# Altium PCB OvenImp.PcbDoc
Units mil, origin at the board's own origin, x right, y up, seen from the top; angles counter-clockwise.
Board outline 3800 x 1750 mil, 2 copper layers (Top Layer, Bottom Layer); 45 components, 37 nets, 177 pads, 107 vias.
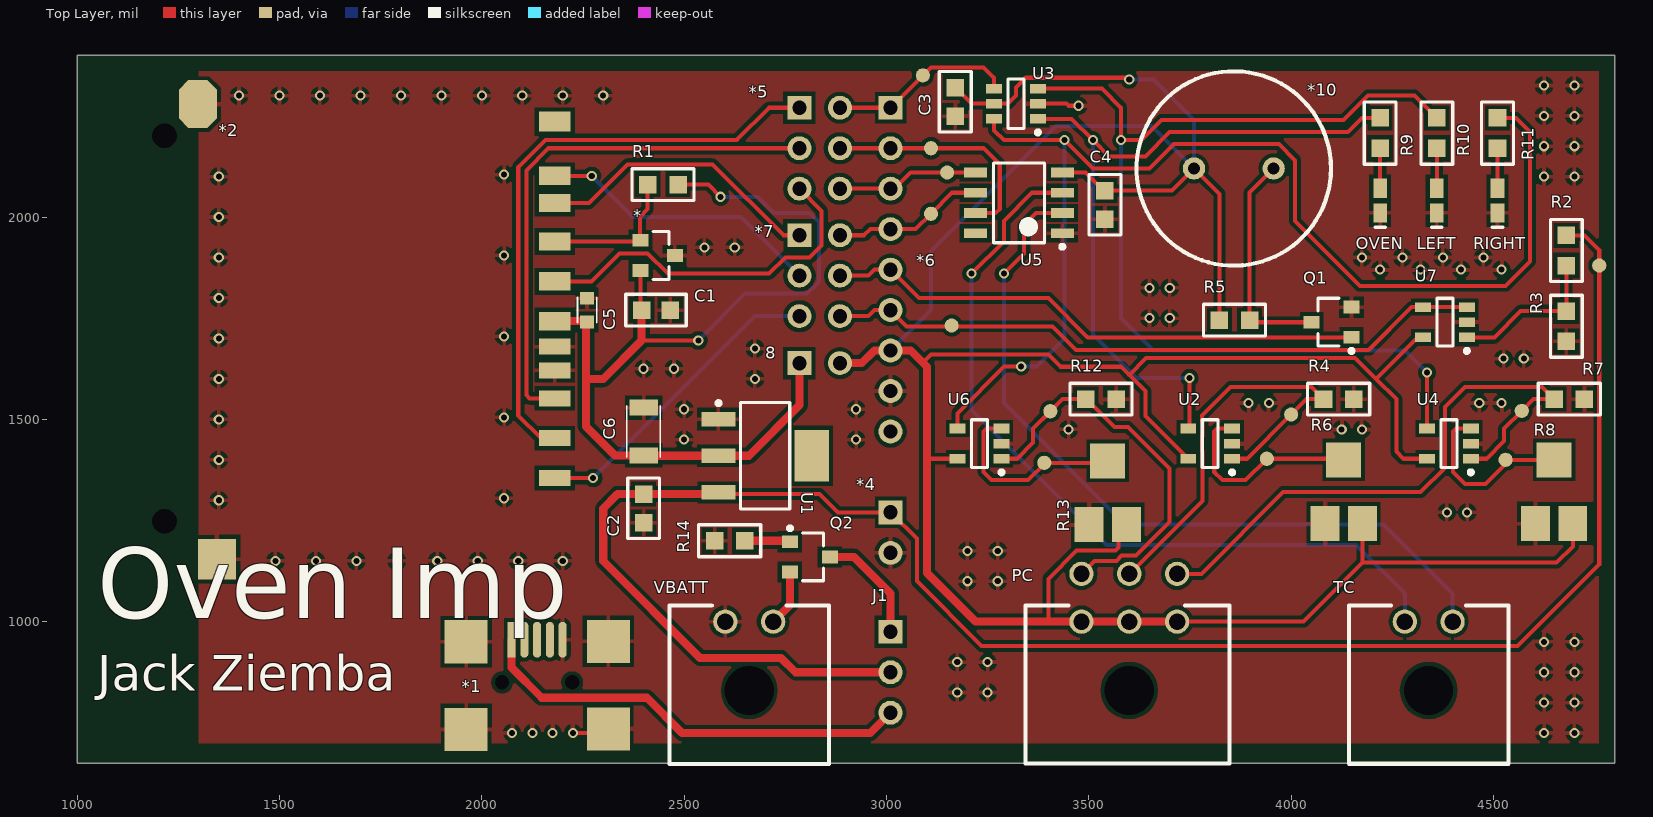
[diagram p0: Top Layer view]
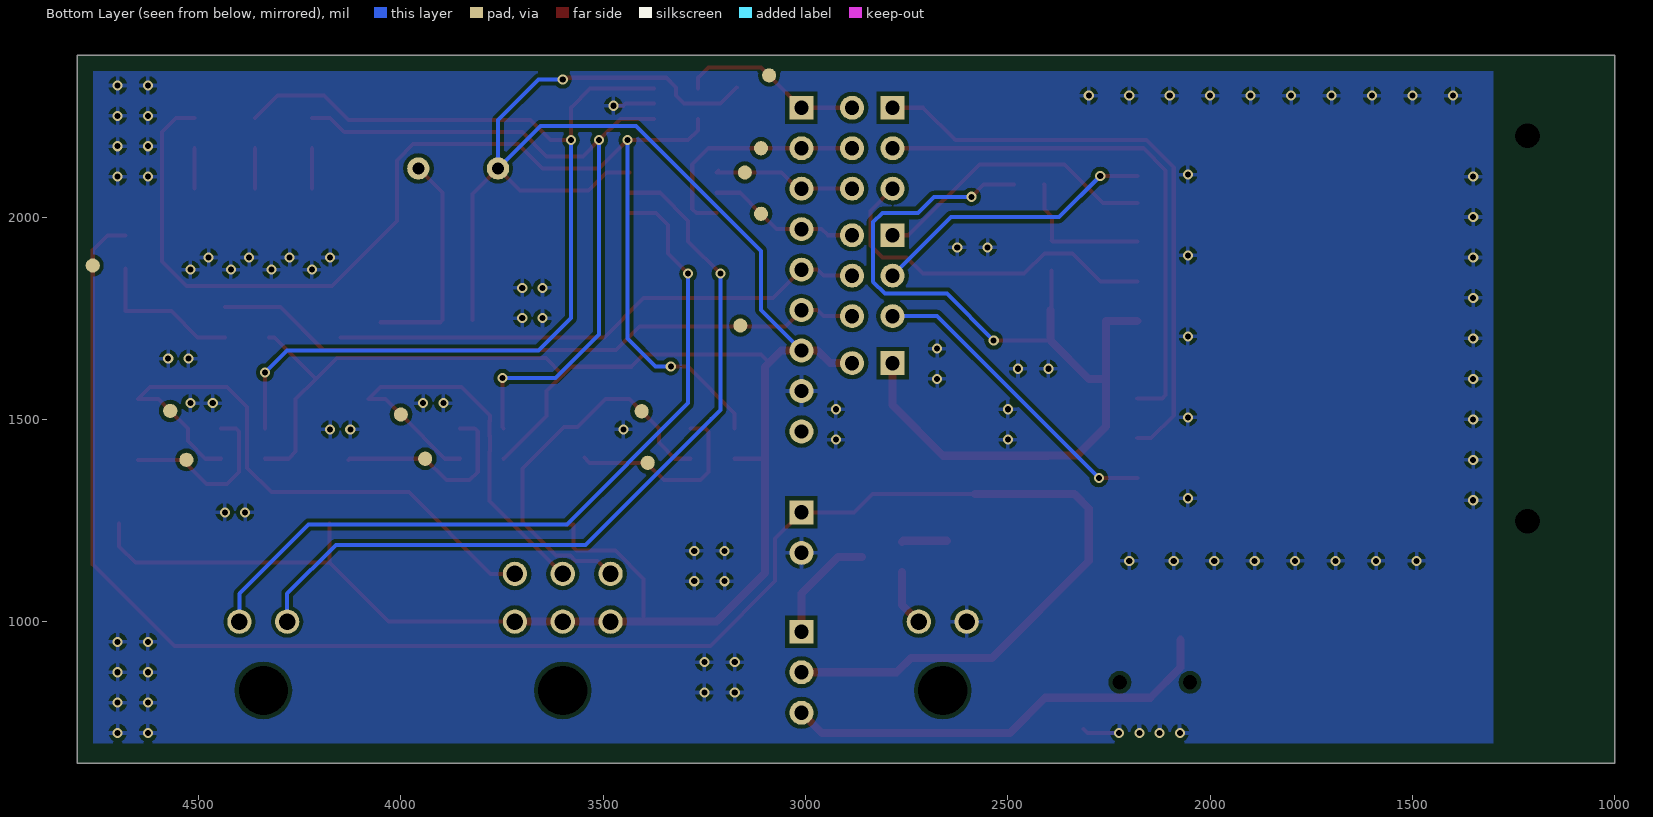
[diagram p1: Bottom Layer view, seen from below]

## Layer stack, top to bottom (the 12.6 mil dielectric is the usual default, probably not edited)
Top Solder: solder mask 0.4, Solder Resist, Dk 3.5
Top Layer: signal copper 1.4
Dielectric 1: dielectric 12.6, FR-4, Dk 4.8
Bottom Layer: signal copper 1.4
Bottom Solder: solder mask 0.4, Solder Resist, Dk 3.5

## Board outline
1000,650 1000,2400 4800,2400 4800,650

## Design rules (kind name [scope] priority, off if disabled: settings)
Clearance [All] p1: gap=8
HoleSize [All] p1: absolutevalues=TRUE maxlimit=200 minlimit=1 maxpercent=80.000 minpercent=20.000
MinimumAnnularRing [All] p1: minimumring=5
PolygonConnect PolygonConnect_2 [All vs IsNamedPolygon('BTM_GND')] p1: connectstyle=Relief reliefconductorwidth=15 reliefentries=4 polygonreliefangle="90 Angle" airgapwidth=10
PolygonConnect PolygonConnect_1 [All vs IsNamedPolygon('TOP_GND')] p2: connectstyle=Relief reliefconductorwidth=15 reliefentries=4 polygonreliefangle="90 Angle" airgapwidth=10
PolygonConnect [All] p3: connectstyle=Relief reliefconductorwidth=10 reliefentries=4 polygonreliefangle="90 Angle" airgapwidth=10
RoutingVias [All] p1: holewidth=25 width=25 viastyle="Through Hole" minholewidth=10 minwidth=15 maxholewidth=30 maxwidth=50
SilkToSilkClearance [All] p1: silktosilkclearance=5
SolderMaskExpansion [All] p1: expansion=6
Width [All] p1: maxlimit=200 minlimit=10 preferedwidth=10
28 further rules are at their usual default settings.

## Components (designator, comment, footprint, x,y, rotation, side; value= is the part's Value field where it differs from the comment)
8 "2 pin header" HDR254P1X2-N 2785,1639 r0 top
* "Crypto ID" SOT23-ATMEL 2435,1905 r180 top
*1 "Mini_USB" 4ucon20035 2137.11,844.59 r0 top
*2 "Imp_Slot" IMP_SLOT_COMBO 1570,1720 r90 top
*4 "2 pin header" HDR254P1X2-N 3010,1270 r270 top
*5 "2 pin header_1" HDR254P2X3-N 2785,2270 r270 top
*6 "April_breakout" HDR254P1X9-N 3010,2270 r270 top
*7 "2 pin header_1" HDR254P2X3-N 2785,1955 r270 top
*10 "AUDIO PIEZO TRANSDUCER 30V TH" "Piezo Buzzer" 3760,2120 r0 top
C1 "0.1uF" 0603_CAPACITOR 2430.43,1770 r180 top
C2 "0.1uF" 0603_CAPACITOR 2400,1280 r90 top
C3 "0.1uF" 0603_CAPACITOR 3170,2284.57 r90 top
C4 "0.1uF" 0603_CAPACITOR 3540,2030 r90 top
C5 "311-1446-1-ND" CAP0603 2260,1770 r270 top
C6 "CC1206ZKY5V7BB106" CAP1206 2400,1470 r270 top
J1 "3 Pin header" HDR254P1X3-N 3010,975 r270 top
LEFT "LED" DIOM1608X03N 4360,2040.51 r90 top
OVEN "LED" DIOM1608X03N 4220,2040.51 r90 top
PC "6 pin mate n lok" 3-794620-6 3481.89,1000.08 r0 top
Q1 "MOSFET N-CH 60V 1.3A SOT23F" SOT95P240X100-3N 4100,1730 r0 top
Q2 "PFET_GOOD" SOT95P240X100-3N 2810.79,1170 r180 top
R1 "100K" 0603_Resistor 2447.6,2080 r0 top
R2 "2K" 0603_Resistor 4680,1917.4 r90 top
R3 "1K" 0603_Resistor 4680,1730 r90 top
R4 "10K" 0603_Resistor 4117.4,1550 r180 top
R5 "1K" 0603_Resistor 3860,1745 r180 top
R6 "TRIMMER 10K OHM 0.25W SMD" "SMD Trimpot" 4130,1242.52 r0 top
R7 "10K" 0603_Resistor 4687.4,1550 r180 top
R8 "TRIMMER 10K OHM 0.25W SMD" "SMD Trimpot" 4650,1242.52 r0 top
R9 "RC0603FR-07220RL" 0603_Resistor 4220,2207.4 r90 top
R10 "RC0603FR-07220RL" 0603_Resistor 4360,2207.4 r90 top
R11 "RC0603FR-07220RL" 0603_Resistor 4510,2207.4 r90 top
R12 "10K" 0603_Resistor 3530,1550 r180 top
R13 "TRIMMER 10K OHM 0.25W SMD" "SMD Trimpot" 3546.74,1240 r0 top
R14 "100K" 0603_Resistor 2612.6,1200 r0 top
RIGHT "LED" DIOM1608X03N 4510,2040.51 r90 top
TC "2pin Micro mate n lok" 3-794620-2 4280.94,1000.08 r0 top
U1 "IC REG LDO 3V3 1A" SOT230P700X180-4N 2700,1410 r0 top
U2 "IC COMPARATOR VOLT SGL SOT23-5" SOT95P280X145-5N 3800,1440 r180 top
U3 "IC OR GATE 3 INPUT SOT23-6" SOT95P280X145-6N 3320,2280 r180 top
U4 "IC COMPARATOR VOLT SGL SOT23-5" SOT95P280X145-5N 4390,1440 r180 top
U5 "IC CONV THERMOCOUPLE-DGTL SOIC" SOIC127P600X175-8N 3327.28,2035 r180 top
U6 "IC COMPARATOR VOLT SGL SOT23-5" SOT95P280X145-5N 3230,1440 r180 top
U7 "IC OPAMP GP 1.3MHZ RRO SOT23-5" SOT95P280X145-5N 4380,1740 r180 top
VBATT "2pin Micro mate n lok" 3-794620-2 2601.89,1000 r0 top

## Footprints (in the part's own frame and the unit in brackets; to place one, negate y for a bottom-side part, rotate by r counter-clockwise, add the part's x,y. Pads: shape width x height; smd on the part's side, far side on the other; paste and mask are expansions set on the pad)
3-794620-2 [mm] "2 Pin TE Micro Mate-N-Lok"
  round 1.524 hole 1.03: 1(3,0) 2(0,0)
  round 0 hole 3.08 paste+0: HOLE(1.5,-4.32)
  silkscreen extent -3.5,-8.92 6.5,1.02
3-794620-6 [mm] "6 Pin TE Micro Mate-N-Lok"
  round 1.524 hole 1.03: 1(6,0) 2(3,0) 3(0,0) 4(0,3) 5(3,3) 6(6,3)
  round 0 hole 3.08 paste+0: HOLE(3,-4.32)
  silkscreen extent -3.5,-8.9 9.3,1
4ucon20035 [mm] "Mini-B USB, Top Mount, Right Angle, SMT"
  rect 0.5x2.25 smd: 1(-1.612,2.813)
  oval 0.5x2.25 smd: 2(-0.812,2.813) 3(-0.012,2.813) 4(0.788,2.813) 5(1.588,2.813)
  round 0 hole 0.9 unplated paste+0 mask+1: H1(-2.213,0.138)
  round 0 hole 0.9 unplated mask+1: H2(2.188,0.138)
  rect 2.7x2.7 smd: M1(-4.463,2.688) M2(4.463,2.712) M3(-4.463,-2.812) M4(4.463,-2.788)
  body extent -4.95,-5.77 4.95,3.23, height 4.08
0603_CAPACITOR [mm]
  rect 1.1x1.1 smd: 1(-0.9,0) 2(0.9,0)
  silkscreen extent -1.9,-1 1.9,1, body extent -0.8,-0.37 0.8,0.43, height 0.6
0603_Resistor [mm]
  rect 1.1x1.1 smd: 1(-0.95,0) 2(0.95,0)
  silkscreen extent -1.95,-1 1.95,1, body extent -0.8,-0.37 0.8,0.43, height 0.46
CAP0603 [mm] "Chip Capacitor, Body 1.6x0.8mm"
  rect 0.8x0.9 smd: 1(-0.75,0) 2(0.75,0)
  silkscreen extent -0.8,-0.6 0.8,0.6, body extent -0.87,-0.45 0.83,0.45, height 0.9
CAP1206 [mm] "Chip Capacitor, Body 3.2x1.6mm"
  rect 1x1.8 smd: 1(-1.5,0) 2(1.5,0)
  silkscreen extent -1.6,-1.05 1.6,1.05, body extent -1.65,-0.85 1.65,0.85, height 0.95
DIOM1608X03N [mm] "Molded Diode, 2-Leads, Body 1.6x0.8mm, IPC Medium Density"
  rect 1.2x0.85 smd: 1(-0.775,0) 2(0.775,0)
  silkscreen extent -1.68,-0.33 -1.68,0.33, body extent -0.85,-0.45 0.85,0.45, height 0.35
HDR254P1X2-N [mm] "HDR, 2.54mm Pitch, 2-Pin"
  rect 1.5x1.5 hole 0.9: 1(0,0)
  round 1.5 hole 0.9: 2(2.54,0)
  body extent -1.27,-1.27 3.81,1.27, height 8.54
HDR254P1X3-N [mm] "HDR, 2.54mm Pitch, 3-Pin"
  rect 1.5x1.5 hole 0.9: 1(0,0)
  round 1.5 hole 0.9: 2(2.54,0) 3(5.08,0)
  body extent -1.27,-1.27 6.35,1.27, height 8.54
HDR254P1X9-N [mm] "HDR, 2.54mm Pitch, 9-Pin"
  rect 1.5x1.5 hole 0.9: 1(0,0)
  round 1.5 hole 0.9: 2(2.54,0) 3(5.08,0) 4(7.62,0) 5(10.16,0) 6(12.7,0) 7(15.24,0) 8(17.78,0) 9(20.32,0)
  body extent -1.27,-1.27 21.59,1.27, height 8.54
HDR254P2X3-N [mm] "HDR, 2.54mm Pitch, 2x3-Pin"
  rect 1.5x1.5 hole 0.9: 1(0,0)
  round 1.5 hole 0.9: 2(0,2.54) 3(2.54,0) 4(2.54,2.54) 5(5.08,0) 6(5.08,2.54)
  body extent -1.27,-1.27 6.35,3.81, height 8.54
IMP_SLOT_COMBO [mm] "Combo Footprint for Kyocera, Proconn and 4UConn"
  rect 1x2 smd: 1(-6.77,-15.5) 2(-4.27,-15.5) 3(-2.52,-15.5) 9(-9.27,-15.5) 10(-1.02,-15.5)
  rect 1.15x2 smd: 4(0.575,-15.5) 5(3.075,-15.5) 6(5.575,-15.5) 7(7.995,-15.5) 8(9.695,-15.5)
  rect 1.25x2 smd: 11(13.095,-15.5)
  oct 3x2.4 smd: 12(14.2,6.9)
  rect 2.55x2.4 smd: 13(-14.375,5.7)
  round 0 hole 1.55 unplated: 14(-11.98,9) 15(12.22,9)
  body extent -14.55,-15.75 13.95,14.5, height 2.65
"Piezo Buzzer" [mm]
  round 1.4 / inner round 1.3 / far side round 1.4 hole 0.75: 1(0,0) 2(5,0)
  silkscreen extent -3.6,-6.1 8.6,6.1, body extent -3.54,-6.08 8.62,6.08, height 7.5
"SMD Trimpot" [mm]
  rect 1.8x2.2 smd: 1(-1.175,0) 3(1.175,0)
  rect 2.2x2.2 smd: 2(0,4)
  body extent -1.9,-0.29 1.9,4.21, height 1.4
SOIC127P600X175-8N [mm] "SOIC, 8-Leads, Body 4.90x3.90mm, Pitch 1.27mm, IPC Medium Density"
  rect 1.45x0.6 smd: 1(-2.725,1.905) 2(-2.725,0.635) 3(-2.725,-0.635) 4(-2.725,-1.905) 5(2.725,-1.905) 6(2.725,-0.635) 7(2.725,0.635) 8(2.725,1.905)
  silkscreen extent -2.85,-2.5 1.6,2.88, body extent -3,-2.5 3,2.5, height 1.75
SOT23-ATMEL [mm] "SOT23 ATSHA204 pinout"
  rect 1x0.8 smd: 1(1.075,-0.95) 2(1.075,0.95) 3(-1.075,0)
  silkscreen extent -0.7,-1.5 0.3,1.5, body extent -1.17,-1.46 1.17,1.46, height 1
SOT95P240X100-3N [mm] "SOT23, 3-Leads, Body 2.90x2.40mm, Pitch 0.95mm, IPC Medium Density"
  rect 1x0.8 smd: 1(1.25,-0.696) 2(1.25,1.204) 3(-1.25,0.254)
  silkscreen extent -0.85,-1.67 1.38,1.75, body extent -1.25,-1.25 1.25,1.75, height 1
SOT95P280X145-5N [mm] "SOT23, 5-Leads, Body 2.90x2.80mm, Pitch 0.95mm, IPC Medium Density"
  rect 1x0.6 smd: 1(-1.375,0.95) 2(-1.375,0) 3(-1.375,-0.95) 4(1.375,-0.95) 5(1.375,0.95)
  silkscreen extent -1.5,-1.5 0.5,1.92, body extent -1.5,-1.5 1.5,1.5, height 1.45
SOT95P280X145-6N [mm] "SOT23, 6-Leads, Body 2.90x2.80mm, Pitch 0.95mm, IPC Medium Density"
  rect 1x0.6 smd: 1(-1.375,0.95) 2(-1.375,0) 3(-1.375,-0.95) 4(1.375,-0.95) 5(1.375,0) 6(1.375,0.95)
  silkscreen extent -1.5,-1.55 0.5,1.92, body extent -1.5,-1.53 1.5,1.53, height 1.45
SOT230P700X180-4N [mm] "SOT223, 4-Leads, Body 6.50x7.00mm (avg), Pitch 2.30mm, IPC Medium Density"
  rect 2.15x0.9 smd: 1(-2.925,2.3) 2(-2.925,0) 3(-2.925,-2.3)
  rect 2.15x3.25 smd: 4(2.925,0)
  silkscreen extent -3.05,-3.35 1.55,3.42, body extent -3.5,-3.35 3.5,3.35, height 1.8

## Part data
C1 C2 C3 C4: library part "CAP CER 0.1UF 50V Y5V 0603", "0.1UF CAP 0603"
C5: library part CC0603KRX7R7BB105, "CAP CER 1UF 16V 10% X7R 0603"
C6: "CAP CER 10UF 16V Y5V 1206"
LEFT OVEN RIGHT: library part LTST-C193KRKT-5A, "LED RED RECT CLEAR 0603"
R1 R14: library part "RES SMD 100K OHM 5% 1/10W 0603", "100K OHM Resistor 5%, 1/10W 0603"
R2: library part "RES SMD 2K OHM 5% 1/10W 0603", "2K OHM Resistor 5%, 1/10W 0603"
R3 R5: library part "RES SMD 1K OHM 5% 1/10W 0603", "1K OHM Resistor 5%, 1/10W 0603"
R4 R7 R12: library part "RES SMD 10K OHM 5% 1/10W 0603", "10K OHM Resistor 5%, 1/10W 0603"
R9 R10 R11: "RES 220 OHM 1/10W 1% 0603 SMD"
U1: "3.3V LDO SOT223"
U2 U4 U6: "Comparator SOT23"
U3: "OR Gate 3 Input"
U5: "Thermocouple to Digital Converter"
U7: "OPAMP SOT23"

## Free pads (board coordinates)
  round 35 all layers, no hole: 2(3090,2350) 2(3110,2008) 2(3110,2170) 2(3150,2110) 2(3161,1732) 2(3390,1392.6) 2(3405,1520) 2(3940,1402.6) 2(4000,1512) 2(4530,1400) 2(4570,1521) 2(4761.46,1880)

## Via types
v1: diameter 25, hole 15, Top Layer to Bottom Layer, tented both sides, 94 vias
v2: diameter 25, hole 15, Top Layer to Bottom Layer, 13 vias

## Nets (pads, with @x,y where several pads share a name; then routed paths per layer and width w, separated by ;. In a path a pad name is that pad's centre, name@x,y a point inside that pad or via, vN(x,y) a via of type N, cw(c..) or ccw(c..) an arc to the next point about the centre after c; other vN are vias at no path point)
3V3: 8.2 *6.7 *10.1 C3.2 C4.2 PC.1 PC.2 PC.3 R5.2 R6.3 R8.3 R13.3 U2.5 U3.5 U4.5 U5.4 U6.5 U7.5 | length 7682.8
  Top Layer w10: 3090,1640 3110,1660 3400,1660 3430,1630 3580,1630 3600,1610 ; 3100,1390 3102.6,1392.6 ; 3100,1410 3107.4,1402.6 U6.5 ; C3.2 3210,2280 U3.5 3300,2280 3320,2300 3320,2320 3344.21,2344.21 3595.79,2344.21 v2(3600,2340) ; 3400,1000.08 3400,1106 3470,1176 3565.89,1176 3573.08,1183.19 3573.08,1240 R13.3 ; U5.4 3491.72,2110 3536.28,2065.43 C4.2 3705.43,2065.43 *10.1 3822.6,2057.4 R5.2 ; PC.1 4030.08,1000.08 4176.26,1146.26 ; U2.5 3640,1508.47 3640,1570 3600,1610 ; R6.3 4176.26,1146.26 ; U7.5 4312.6,1702.6 4210,1600 ; U4.5 4277.4,1402.6 4260,1420 4260,1550 4210,1600 ; R8.3 4696.26,1186.26 4656.26,1146.26 4176.26,1146.26 ; 3600,1610 3641.85,1651.85 4158.15,1651.85 4210,1600
  Top Layer w20: 8.2 2939,1639 2970,1670 *6.7 3060,1670 3090,1640 3100,1630 3100,1410 3100,1390 3100,1120 3219.92,1000.08 3400,1000.08 PC.3 PC.2 PC.1
  Bottom Layer w10: *6.7 3110,1770 3110,1916.57 3418.43,2225 3655,2225 *10.1 3760,2240 3660,2340 v2(3600,2340)
3V3_I: 8.1 *2.4 *.2 C1.2 C5.2 C6.2 R1.2 U1.2 | length 2432.7
  Top Layer w10: *.2 2392.68,1772.32 C1.2 ; 2395,1695 v2(2535,1695) ; R1.2 2560,2080 v2(2590,2050)
  Top Layer w20: *2.4 2257.83,1742.64 2257.83,1600 ; C1.2 2395,1695 2300,1600 2257.83,1600 ; 8.1 2785,1535 2660,1410 U1.2 2400.94,1410 C6.2 2329.06,1410.94 2257.83,1482.17 2257.83,1600
  Bottom Layer w10: v2(2535,1695) 2650.47,1810.47 2803.44,1810.47 2832.97,1840 2832.97,1987.3 2810.27,2010 2722.03,2010 2682.03,2050 v2(2590,2050)
ALARM: *6.5 *7.4 Q1.1 | length 1339.8
  Top Layer w10: *7.4 2955,1855 2970,1870 *6.5 3080,1800 3400,1800 3497.4,1702.6 Q1.1
ALARM_I: *2.8 *7.3 | length 706.9
  Top Layer w10: *2.8 v2(2271.69,2101.69)
  Bottom Layer w10: v2(2271.69,2101.69) 2373.39,2000 2640,2000 *7.3
BATT_VOLTAGE: *6.6 *7.6 pad.2@3161,1732 U7.3 U7.4 | length 1639.7
  Top Layer w10: *7.6 2955,1755 2970,1770 *6.6 3050,1730 3410,1730 3468.15,1671.85 4191.85,1671.85 4297.4,1777.4 U7.4 U7.3
BATT_VOLTAGE_I: *2.9 *7.5 | length 770.4
  Top Layer w10: *2.9 v2(2275.04,1355.04)
  Bottom Layer w10: v2(2275.04,1355.04) 2675,1755 *7.5
C\S\: *6.4 *7.2 pad.2@3110,2008 U5.6 | length 378.5
  Top Layer w10: *7.2 2945,1955 2960,1970 *6.4 3072,1970 3110,2008 3162,2060 U5.6
C\S\_I: *2.7 *7.1 | length 716.7
  Top Layer w10: *2.7 2264.76,2034.76 2360,2130 2570,2130 2745,1955 *7.1
GND: *1.5 *1.M1 *1.M2 *1.M3 *1.M4 *2.3 *2.10 *2.12 *2.13 *4.2 *6.8 *.3 C1.1 C2.1 C3.1 C4.1 C5.1 C6.1 LEFT.1 OVEN.1 Q1.2 R3.1 R4.1 R6.1 R7.1 R8.1 R12.1 R13.1 R14.1 RIGHT.1 U1.1 U2.2 U3.2 U4.2 U5.1 U6.2 U7.2 VBATT.2 | length 194.8
  Top Layer w10: v1(2225,725) 2302.95,725 *1.M4 ; U3.2 3445,2280 3450,2275 v1(3475,2275)
  other v1: 2075,725 2125,725 2175,725 4625,725 4700,725 4625,800 4700,800 3175,825 3250,825 4625,875 4700,875 3175,900 3250,900 4625,950 4700,950 3200,1100 3275,1100 1490,1150 1590,1150 1690,1150 1790,1150 1890,1150 1990,1150 2090,1150 2200,1150 3200,1175 3275,1175 4385,1270 4435,1270 1350,1300 2055,1305 1350,1400 2500,1450 2925,1450 3450,1475 4125,1475 4175,1475 1350,1500 2055,1505 2500,1525 2925,1525 3895,1540 3945,1540 4465,1540 4520,1540 1350,1600 2675,1600 2400,1625 2475,1625 4525,1650 4575,1650 2675,1675 1350,1700 2055,1705 3650,1750 3700,1750 1350,1800 3650,1825 3700,1825 4220,1870 4320,1870 4420,1870 4520,1870 1350,1900 4175,1900 4275,1900 4375,1900 4475,1900 2055,1905 2550,1925 2625,1925 1350,2000 1350,2100 4625,2100 4700,2100 2055,2105 4625,2175 4700,2175 4625,2250 4700,2250 1400,2300 1500,2300 1600,2300 1700,2300 1800,2300 1900,2300 2000,2300 2100,2300 2200,2300 2300,2300 4625,2325 4700,2325
LEFT_LIGHT: R10.2 U3.3 U4.4 | length 2533.8
  Top Layer w10: U3.3 3532.6,2317.4 3580,2270 v2(3580,2190) 3630,2190 3680,2240 4130,2240 4190,2300 4304.8,2300 R10.2 ; U4.4 v2@4335.87,1605.87
  Bottom Layer w10: v2(3580,2190) 3580,1750 3660,1670 4281.73,1670 v2(4335.87,1615.87)
LEFT_LIGHT_-: pad.2@4570,1521 PC.6 R7.2 U4.1 | length 1508.6
  Top Layer w10: PC.6 3778.19,1118.19 3980,1320 4320,1320 4380,1380 4380,1530 4430,1580 4620,1580 R7.2 4599,1550 4570,1521 4526.4,1477.4 4526.4,1446.4 4482.6,1402.6 U4.1
MISO: *5.4 *6.2 pad.2@3110,2170 U5.7 | length 585.7
  Top Layer w10: *5.4 *6.2 3240,2170 3280,2130 3280,2020 3270,2010 U5.7
MISO_I: *2.2 *5.3 | length 1326.2
  Top Layer w10: *2.2 2118.11,1551.89 2110,1560 2110,2114.68 2165.32,2170 *5.3
Net*2_6: *2.6 *.1 R1.1 | length 357.3
  Top Layer w10: *2.6 2389.76,1939.49 *.1 ; *.1@2390.59,1944.49 2390.59,2000.59 2410,2020 2410,2079.8 R1.1
Net*10_2: *10.2 Q1.3 R5.1 | length 555.1
  Top Layer w10: *10.2 3897.4,2060.55 R5.1 3902.4,1740 Q1.3
NetLEFT_2: LEFT.2 R10.1 | length 99
  Top Layer w10: LEFT.2 R10.1
NetOVEN_2: OVEN.2 R9.1 | length 99
  Top Layer w10: OVEN.2 R9.1
NetQ2_1: Q2.1 R14.2 | length 112.7
  Top Layer w20: R14.2 2758.98,1200 Q2.1
NetR2_1: R2.1 R3.2 U7.1 | length 377.9
  Top Layer w10: U7.1 4502.6,1702.6 4567.4,1767.4 R3.2 R2.1@4680,1872.6
NetR6_2: pad.2@3940,1402.6 R6.2 U2.3 | length 498.3
  Top Layer w10: U2.3 3817.4,1477.4 3810,1470 3810,1370 3830,1350 3887.4,1350 3940,1402.6 4127.4,1402.6 R6.2
NetR8_2: pad.2@4530,1400 R8.2 U4.3 | length 440.3
  Top Layer w10: U4.3 4407.4,1477.4 4400,1470 4400,1370 4430,1340 4480,1340 4530,1390 4530,1400 R8.2
NetR11_1: R11.1 RIGHT.2 | length 99
  Top Layer w10: RIGHT.2 R11.1
NetR13_2: pad.2@3390,1392.6 R13.2 U6.3 | length 487.8
  Top Layer w10: U6.3 3247.4,1477.4 3240,1470 3240,1370 3260,1350 3350,1350 pad.2@3392.6,1392.6 ; pad.2@3390,1392.6 pad.2@3392.6,1392.6 ; R13.2@3546.74,1405.48 3533.86,1392.6 pad.2@3392.6,1392.6
OVEN_LIGHT: R9.2 U2.4 U3.1 | length 1813.1
  Top Layer w10: U3.1 3457.4,2242.6 v2(3510,2190) 3550,2150 3640,2150 3700,2210 4140,2210 4174.8,2244.8 R9.2 ; U2.4 3749,1480.54 v2(3749,1602)
  Bottom Layer w10: v2(3510,2190) 3510,1710 3618,1602 v2(3749,1602)
OVEN_LIGHT_-: pad.2@4000,1512 PC.5 R4.2 U2.1 | length 1095.6
  Top Layer w10: PC.5 3780.55,1298.74 3780.55,1420.62 3780,1421.18 3780,1458.83 3780.55,1459.38 3780.55,1495.43 3780,1495.98 3780,1510 3850,1580 4050,1580 R4.2 4038,1550 4000,1512 3890.6,1402.6 U2.1
RIGHT_LIGHT: R11.2 U3.6 U6.4 | length 2958.1
  Top Layer w10: U6.4 3175,1478.27 3175,1515 3291,1631 v2(3333,1631) ; U3.6 3265.87,2214.13 3290,2190 v2(3440,2190) 3510,2120 3650,2120 3710,2180 3970,2180 4010,2140 4010,1990 4170,1830 4530,1830 4590,1890 4590,2210 4555.2,2244.8 R11.2
  Bottom Layer w10: v2(3333,1631) 3371,1631 3440,1700 v2(3440,2190)
RIGHT_LIGHT_-: pad.2@3405,1520 PC.4 R12.2 U6.1 | length 971.4
  Top Layer w10: U6.1 3322.6,1402.6 3362.4,1442.4 3362.4,1477.4 3405,1520 3435,1550 R12.2 3494.05,1550 3563.05,1481 3597,1481 3700,1378 3700,1246.47 3616.72,1163.19 3581.36,1163.19 3568.17,1150 3513.7,1150 PC.4
SCK: *5.6 *6.3 pad.2@3150,2110 U5.5 | length 358.6
  Top Layer w10: *5.6 *6.3 3020,2070 3060,2110 U5.5 U5.5@3215,2115
SCK_I: *2.5 *5.5 | length 901
  Top Layer w10: *2.5 2271.06,1841.06 2340,1910 2410,1910 2460,1860 2710,1860 2750,1900 2810.27,1900 2840,1929.73 2840,2015 *5.5
TC+: TC.2 U5.3 | length 2001.4
  Top Layer w10: v2(3210,1860) 3290,1940 3290,1990 3360,2060 U5.3
  Bottom Layer w10: v2(3210,1860) 3210,1523.43 3231.72,1501.72 3543.43,1190 4160,1190 4280.94,1069.06 TC.2
TC-: TC.1 U5.2 | length 1940.8
  Top Layer w10: v2(3290,1860) 3340,1910 3340,1980 3370,2010 U5.2
  Bottom Layer w10: v2(3290,1860) 3290,1540 3590,1240 4228.11,1240 4399.06,1069.06 TC.1
VBATT+: Q2.2 VBATT.1 | length 139.8
  Top Layer w20: VBATT.1 2761.57,1041.57 Q2.2
VBATT_PROT: J1.1 Q2.3 | length 282.3
  Top Layer w20: Q2.3 2920,1160 3010,1070 J1.1
VBUS: *1.1 J1.3 | length 1092.9
  Top Layer w20: *1.1 2073.62,886.38 2148,812 2408,812 2495,725 2960,725 J1.3
VIN: *4.1 C2.2 J1.2 pad.2@4761.46,1880 R2.2 U1.3 | length 4604.1
  Top Layer w10: U1.3@2580.83,1315.43 2834.57,1315.43 2880,1270 *4.1 3075,1205 3075,1100 3235,940 4560,940 4761.46,1141.46 4761.46,1880 4761.46,1918.54 4725.2,1954.8 R2.2
  Top Layer w20: U1.3@2580.83,1315.43 C2.2 2335.43,1315.43 2300,1280 2300,1150 2539.45,910.55 2739.45,910.55 2775,875 J1.2
WAKEUP: *5.2 *6.1 pad.2@3090,2350 U3.4 | length 459.7
  Top Layer w10: *5.2 *6.1 3110,2370 3240,2370 3265.87,2344.13 U3.4
WAKEUP_I: *2.1 *5.1 | length 1482.5
  Top Layer w10: *2.1 2146.54,1453.46 2090,1510 2090,2122.96 2157.04,2190 2630,2190 2710,2270 *5.1
pads on no net: *1.2 *1.3 *1.4 *1.H1 *1.H2 *2.11 *2.14 *2.15 *6.9 PC.HOLE TC.HOLE U1.4 U5.8 VBATT.HOLE

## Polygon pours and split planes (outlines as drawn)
GND on Top Layer "Top GND" (solid, pour order 2): 1300,700 1300,2360 4760,2360 4760,700
GND on Bottom Layer "Bottom GND" (solid, pour order 4): 1300,700 1300,2360 4760,2360 4760,700

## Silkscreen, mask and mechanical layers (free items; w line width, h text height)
Top Overlay:
  text "Oven Imp" at 1050,950 h300
  text "Jack Ziemba" at 1050,800 h150
Mechanical 1:
  the board outline again, w10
